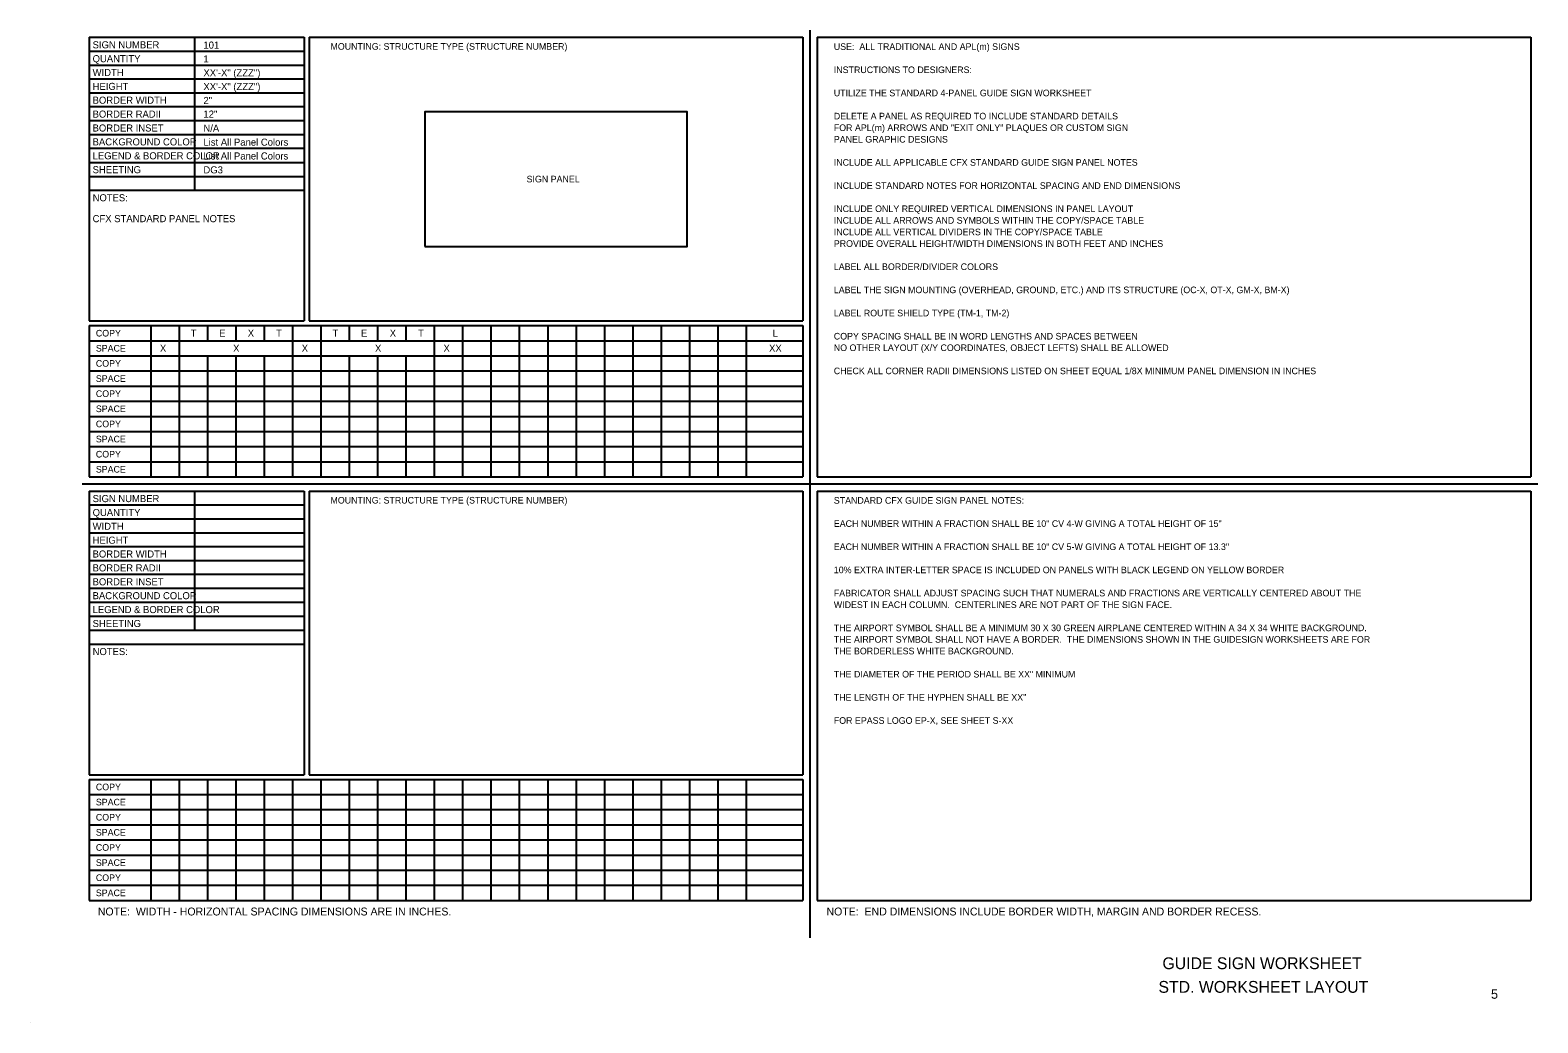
# Model space of a CAD drawing. Extents: x 10268312 to 10268472, y 2142583 to 2142688.
import ezdxf

# ---------------------------------------------------------------- set-up
doc = ezdxf.new("R2010")
doc.units = 0
for name, color, linetype in [('AdhocPoint_dp', 7, 'Continuous'), ('GSDims', 7, 'Continuous'), ('SheetBorder_dp', 7, 'Continuous'), ('SumBoxLines_dp', 7, 'Continuous'), ('SumBoxLinesMin_dp', 7, 'Continuous'), ('TextMisc', 7, 'Continuous'), ('TextNotes', 7, 'Continuous'), ('TextShtNo', 7, 'Continuous')]:
    doc.layers.add(name, color=color, linetype=linetype)

msp = doc.modelspace()

# ---------------------------------------------------------------- linework, layer by layer
at = {"layer": 'AdhocPoint_dp'}
msp.add_line((10268312.23, 2142583.28), (10268312.23, 2142583.28), dxfattribs=at)
at = {"layer": 'SheetBorder_dp'}
for p, q in [((10268394.73, 2142688.28), (10268394.73, 2142592.28)), ((10268317.73, 2142640.28), (10268471.73, 2142640.28))]:
    msp.add_line(p, q, dxfattribs=at)
at = {"layer": 'SumBoxLines_dp'}
for p, q in [((10268318.48, 2142687.53), (10268318.48, 2142657.53)), ((10268318.48, 2142687.53), (10268341.23, 2142687.53)), ((10268329.6, 2142687.53), (10268329.6, 2142671.34)), ((10268341.23, 2142687.53), (10268341.23, 2142657.53)), ((10268341.73, 2142687.53), (10268341.73, 2142657.53)), ((10268341.73, 2142687.53), (10268393.98, 2142687.53)), ((10268393.98, 2142687.53), (10268393.98, 2142657.53)), ((10268395.48, 2142687.53), (10268470.98, 2142687.53)), ((10268395.48, 2142687.53), (10268395.48, 2142641.03)), ((10268470.98, 2142687.53), (10268470.98, 2142641.03)), ((10268318.48, 2142686.07), (10268341.23, 2142686.07)), ((10268318.48, 2142684.59), (10268341.23, 2142684.59)), ((10268318.48, 2142683.12), (10268341.23, 2142683.12)), ((10268318.48, 2142681.66), (10268341.23, 2142681.66)), ((10268318.48, 2142680.19), (10268341.23, 2142680.19)), ((10268318.48, 2142678.73), (10268341.23, 2142678.73)), ((10268318.48, 2142677.26), (10268341.23, 2142677.26)), ((10268318.48, 2142675.79), (10268341.23, 2142675.79)), ((10268318.48, 2142674.28), (10268341.23, 2142674.28)), ((10268318.48, 2142672.81), (10268341.23, 2142672.81)), ((10268318.48, 2142671.34), (10268341.23, 2142671.34)), ((10268318.48, 2142657.53), (10268341.23, 2142657.53)), ((10268341.73, 2142657.53), (10268393.98, 2142657.53)), ((10268318.48, 2142657.03), (10268393.98, 2142657.03)), ((10268318.48, 2142657.03), (10268318.48, 2142641.03)), ((10268324.98, 2142657.03), (10268324.98, 2142641.03)), ((10268327.98, 2142657.03), (10268327.98, 2142641.03)), ((10268330.98, 2142657.03), (10268330.98, 2142655.43)), ((10268333.98, 2142657.03), (10268333.98, 2142655.43)), ((10268336.98, 2142657.03), (10268336.98, 2142655.43)), ((10268339.98, 2142657.03), (10268339.98, 2142653.83)), ((10268342.98, 2142657.03), (10268342.98, 2142653.83)), ((10268345.98, 2142657.03), (10268345.98, 2142655.43)), ((10268348.98, 2142657.03), (10268348.98, 2142655.43)), ((10268351.98, 2142657.03), (10268351.98, 2142655.43)), ((10268354.98, 2142657.03), (10268354.98, 2142655.43)), ((10268357.98, 2142657.03), (10268357.98, 2142655.43)), ((10268360.98, 2142657.03), (10268360.98, 2142653.83)), ((10268363.98, 2142657.03), (10268363.98, 2142653.83)), ((10268366.98, 2142657.03), (10268366.98, 2142653.83)), ((10268369.98, 2142657.03), (10268369.98, 2142653.83)), ((10268372.98, 2142657.03), (10268372.98, 2142655.43)), ((10268375.98, 2142657.03), (10268375.98, 2142655.43)), ((10268378.98, 2142657.03), (10268378.98, 2142655.43)), ((10268381.98, 2142657.03), (10268381.98, 2142655.43)), ((10268384.98, 2142657.03), (10268384.98, 2142655.43)), ((10268387.98, 2142657.03), (10268387.98, 2142655.43)), ((10268393.98, 2142657.03), (10268393.98, 2142641.03)), ((10268354.98, 2142655.43), (10268354.98, 2142641.03)), ((10268357.98, 2142655.43), (10268357.98, 2142641.03)), ((10268372.98, 2142655.43), (10268372.98, 2142641.03)), ((10268375.98, 2142655.43), (10268375.98, 2142641.03)), ((10268378.98, 2142655.43), (10268378.98, 2142649.03)), ((10268381.98, 2142655.43), (10268381.98, 2142649.03)), ((10268384.98, 2142655.43), (10268384.98, 2142649.03)), ((10268387.98, 2142655.43), (10268387.98, 2142641.03)), ((10268318.48, 2142653.83), (10268393.98, 2142653.83)), ((10268330.98, 2142653.83), (10268330.98, 2142641.03)), ((10268333.98, 2142653.83), (10268333.98, 2142641.03)), ((10268336.98, 2142653.83), (10268336.98, 2142641.03)), ((10268339.98, 2142653.83), (10268339.98, 2142641.03)), ((10268342.98, 2142653.83), (10268342.98, 2142641.03)), ((10268345.98, 2142653.83), (10268345.98, 2142641.03)), ((10268348.98, 2142653.83), (10268348.98, 2142641.03)), ((10268351.98, 2142653.83), (10268351.98, 2142641.03)), ((10268360.98, 2142653.83), (10268360.98, 2142641.03)), ((10268363.98, 2142653.83), (10268363.98, 2142641.03)), ((10268366.98, 2142653.83), (10268366.98, 2142649.03)), ((10268369.98, 2142653.83), (10268369.98, 2142649.03)), ((10268318.48, 2142650.63), (10268393.98, 2142650.63)), ((10268366.98, 2142649.03), (10268366.98, 2142641.03)), ((10268369.98, 2142649.03), (10268369.98, 2142641.03)), ((10268378.98, 2142649.03), (10268378.98, 2142641.03)), ((10268381.98, 2142649.03), (10268381.98, 2142641.03)), ((10268384.98, 2142649.03), (10268384.98, 2142641.03)), ((10268318.48, 2142647.43), (10268393.98, 2142647.43)), ((10268318.48, 2142644.23), (10268393.98, 2142644.23)), ((10268318.48, 2142641.03), (10268393.98, 2142641.03)), ((10268395.48, 2142641.03), (10268470.98, 2142641.03)), ((10268318.48, 2142639.53), (10268318.48, 2142609.53)), ((10268318.48, 2142639.53), (10268341.23, 2142639.53)), ((10268318.48, 2142638.07), (10268341.23, 2142638.07)), ((10268329.6, 2142639.53), (10268329.6, 2142624.81)), ((10268341.23, 2142639.53), (10268341.23, 2142609.53)), ((10268341.73, 2142639.53), (10268341.73, 2142609.53)), ((10268341.73, 2142639.53), (10268393.98, 2142639.53)), ((10268393.98, 2142639.53), (10268393.98, 2142609.53)), ((10268395.48, 2142639.53), (10268395.48, 2142596.23)), ((10268395.48, 2142639.53), (10268470.98, 2142639.53)), ((10268470.98, 2142639.53), (10268470.98, 2142596.23)), ((10268318.48, 2142636.59), (10268341.23, 2142636.59)), ((10268318.48, 2142635.12), (10268341.23, 2142635.12)), ((10268318.48, 2142633.66), (10268341.23, 2142633.66)), ((10268318.48, 2142632.19), (10268341.23, 2142632.19)), ((10268318.48, 2142630.73), (10268341.23, 2142630.73)), ((10268318.48, 2142629.26), (10268341.23, 2142629.26)), ((10268318.48, 2142627.79), (10268341.23, 2142627.79)), ((10268318.48, 2142626.28), (10268341.23, 2142626.28)), ((10268318.48, 2142624.81), (10268341.23, 2142624.81)), ((10268318.48, 2142623.34), (10268341.23, 2142623.34)), ((10268318.48, 2142609.53), (10268341.23, 2142609.53)), ((10268341.73, 2142609.53), (10268393.98, 2142609.53)), ((10268318.48, 2142609.03), (10268393.98, 2142609.03)), ((10268318.48, 2142609.03), (10268318.48, 2142596.23)), ((10268324.98, 2142609.03), (10268324.98, 2142596.23)), ((10268327.98, 2142609.03), (10268327.98, 2142596.23)), ((10268330.98, 2142609.03), (10268330.98, 2142596.23)), ((10268333.98, 2142609.03), (10268333.98, 2142596.23)), ((10268336.98, 2142609.03), (10268336.98, 2142596.23)), ((10268339.98, 2142609.03), (10268339.98, 2142596.23)), ((10268342.98, 2142609.03), (10268342.98, 2142596.23)), ((10268345.98, 2142609.03), (10268345.98, 2142596.23)), ((10268348.98, 2142609.03), (10268348.98, 2142596.23)), ((10268351.98, 2142609.03), (10268351.98, 2142596.23)), ((10268354.98, 2142609.03), (10268354.98, 2142596.23)), ((10268357.98, 2142609.03), (10268357.98, 2142596.23)), ((10268360.98, 2142609.03), (10268360.98, 2142596.23)), ((10268363.98, 2142609.03), (10268363.98, 2142596.23)), ((10268366.98, 2142609.03), (10268366.98, 2142596.23)), ((10268369.98, 2142609.03), (10268369.98, 2142596.23)), ((10268372.98, 2142609.03), (10268372.98, 2142596.23)), ((10268375.98, 2142609.03), (10268375.98, 2142596.23)), ((10268378.98, 2142609.03), (10268378.98, 2142596.23)), ((10268381.98, 2142609.03), (10268381.98, 2142596.23)), ((10268384.98, 2142609.03), (10268384.98, 2142596.23)), ((10268387.98, 2142609.03), (10268387.98, 2142607.43)), ((10268393.98, 2142609.03), (10268393.98, 2142596.23)), ((10268387.98, 2142607.43), (10268387.98, 2142596.23)), ((10268318.48, 2142605.83), (10268393.98, 2142605.83)), ((10268318.48, 2142602.63), (10268393.98, 2142602.63)), ((10268318.48, 2142599.43), (10268393.98, 2142599.43)), ((10268318.48, 2142596.23), (10268393.98, 2142596.23)), ((10268395.48, 2142596.23), (10268470.98, 2142596.23))]:
    msp.add_line(p, q, dxfattribs=at)
at = {"layer": 'SumBoxLinesMin_dp'}
for p, q in [((10268318.48, 2142655.43), (10268393.98, 2142655.43)), ((10268318.48, 2142652.23), (10268393.98, 2142652.23)), ((10268318.48, 2142649.03), (10268393.98, 2142649.03)), ((10268318.48, 2142645.83), (10268393.98, 2142645.83)), ((10268318.48, 2142642.63), (10268393.98, 2142642.63)), ((10268318.48, 2142607.43), (10268393.98, 2142607.43)), ((10268318.48, 2142604.23), (10268393.98, 2142604.23)), ((10268318.48, 2142601.03), (10268393.98, 2142601.03)), ((10268318.48, 2142597.83), (10268393.98, 2142597.83))]:
    msp.add_line(p, q, dxfattribs=at)
at = {"layer": 'TextMisc'}
msp.add_lwpolyline([(10268353.98, 2142665.41), (10268381.73, 2142665.41), (10268381.73, 2142679.66), (10268353.98, 2142679.66)], close=True, dxfattribs=at)

# ---------------------------------------------------------------- texts
at = {"layer": 'GSDims'}
for s, height, p in [('MOUNTING: STRUCTURE TYPE (STRUCTURE NUMBER)', 0.7, (10268344, 2142686.21)), ('SIGN PANEL', 0.7, (10268364.75, 2142672.18)), ('T', 0.75, (10268329.21, 2142655.86)), ('E', 0.75, (10268332.22, 2142655.86)), ('X', 0.75, (10268335.25, 2142655.86)), ('T', 0.75, (10268338.25, 2142655.86)), ('T', 0.75, (10268344.22, 2142655.86)), ('E', 0.75, (10268347.23, 2142655.86)), ('X', 0.75, (10268350.27, 2142655.86)), ('T', 0.75, (10268353.27, 2142655.86)), ('L', 0.75, (10268390.77, 2142655.86)), ('X', 0.75, (10268325.96, 2142654.26)), ('X', 0.75, (10268333.7, 2142654.26)), ('X', 0.75, (10268340.96, 2142654.26)), ('X', 0.75, (10268348.71, 2142654.26)), ('X', 0.75, (10268355.96, 2142654.26)), ('XX', 0.75, (10268390.4, 2142654.26)), ('MOUNTING: STRUCTURE TYPE (STRUCTURE NUMBER)', 0.7, (10268344, 2142638.21))]:
    msp.add_text(s, height=height, dxfattribs=at).set_placement(p)
at = {"layer": 'TextMisc'}
for s, height, p in [('SIGN NUMBER', 0.7476, (10268318.84, 2142686.36)), ('101', 0.75, (10268330.56, 2142686.33)), ('USE:  ALL TRADITIONAL AND APL(m) SIGNS', 0.7, (10268397.25, 2142686.19)), ('QUANTITY', 0.748, (10268318.84, 2142684.89)), ('1', 0.75, (10268330.56, 2142684.87)), ('INSTRUCTIONS TO DESIGNERS:', 0.7, (10268397.25, 2142683.74)), ('WIDTH', 0.748, (10268318.84, 2142683.43)), ('HEIGHT', 0.748, (10268318.84, 2142681.96)), ('XX\'-X" (ZZZ")', 0.75, (10268330.56, 2142683.4)), ('XX\'-X" (ZZZ")', 0.75, (10268330.56, 2142681.94)), ('BORDER WIDTH', 0.7476, (10268318.84, 2142680.5)), ('2"', 0.75, (10268330.56, 2142680.47)), ('UTILIZE THE STANDARD 4-PANEL GUIDE SIGN WORKSHEET', 0.7, (10268397.25, 2142681.29)), ('BORDER RADII', 0.7476, (10268318.84, 2142679.03)), ('12"', 0.75, (10268330.56, 2142679.03)), ('DELETE A PANEL AS REQUIRED TO INCLUDE STANDARD DETAILS', 0.7, (10268397.25, 2142678.84)), ('BORDER INSET', 0.7476, (10268318.84, 2142677.56)), ('N/A', 0.75, (10268330.56, 2142677.53)), ('FOR APL(m) ARROWS AND "EXIT ONLY" PLAQUES OR CUSTOM SIGN', 0.7, (10268397.25, 2142677.61)), ('BACKGROUND COLOR', 0.7476, (10268318.84, 2142676.09)), ('List All Panel Colors', 0.75, (10268330.56, 2142676.06)), ('PANEL GRAPHIC DESIGNS', 0.7, (10268397.25, 2142676.39)), ('LEGEND & BORDER COLOR', 0.7476, (10268318.84, 2142674.62)), ('List All Panel Colors', 0.75, (10268330.56, 2142674.6)), ('INCLUDE ALL APPLICABLE CFX STANDARD GUIDE SIGN PANEL NOTES', 0.7, (10268397.25, 2142673.94)), ('SHEETING', 0.748, (10268318.84, 2142673.15)), ('DG3', 0.75, (10268330.56, 2142673.13)), ('INCLUDE STANDARD NOTES FOR HORIZONTAL SPACING AND END DIMENSIONS', 0.7, (10268397.25, 2142671.49)), ('NOTES:', 0.748, (10268318.84, 2142670.18)), ('CFX STANDARD PANEL NOTES', 0.75, (10268318.84, 2142667.97)), ('INCLUDE ONLY REQUIRED VERTICAL DIMENSIONS IN PANEL LAYOUT', 0.7, (10268397.25, 2142669.04)), ('INCLUDE ALL ARROWS AND SYMBOLS WITHIN THE COPY/SPACE TABLE', 0.7, (10268397.25, 2142667.81)), ('INCLUDE ALL VERTICAL DIVIDERS IN THE COPY/SPACE TABLE', 0.7, (10268397.25, 2142666.59)), ('PROVIDE OVERALL HEIGHT/WIDTH DIMENSIONS IN BOTH FEET AND INCHES', 0.7, (10268397.25, 2142665.36)), ('LABEL ALL BORDER/DIVIDER COLORS', 0.7, (10268397.25, 2142662.91)), ('LABEL THE SIGN MOUNTING (OVERHEAD, GROUND, ETC.) AND ITS STRUCTURE (OC-X, OT-X, GM-X, BM-X)', 0.7, (10268397.25, 2142660.46)), ('LABEL ROUTE SHIELD TYPE (TM-1, TM-2)', 0.7, (10268397.25, 2142658.01)), ('COPY', 0.7, (10268319.18, 2142655.88)), ('COPY SPACING SHALL BE IN WORD LENGTHS AND SPACES BETWEEN', 0.7, (10268397.25, 2142655.56)), ('SPACE', 0.7, (10268319.18, 2142654.28)), ('NO OTHER LAYOUT (X/Y COORDINATES, OBJECT LEFTS) SHALL BE ALLOWED', 0.7, (10268397.25, 2142654.34)), ('COPY', 0.7, (10268319.18, 2142652.68)), ('CHECK ALL CORNER RADII DIMENSIONS LISTED ON SHEET EQUAL 1/8X MINIMUM PANEL DIMENSION IN INCHES', 0.7, (10268397.25, 2142651.89)), ('SPACE', 0.7, (10268319.18, 2142651.08)), ('COPY', 0.7, (10268319.18, 2142649.48)), ('SPACE', 0.7, (10268319.18, 2142647.88)), ('COPY', 0.7, (10268319.18, 2142646.28)), ('SPACE', 0.7, (10268319.18, 2142644.68)), ('COPY', 0.7, (10268319.18, 2142643.08)), ('SPACE', 0.7, (10268319.18, 2142641.48)), ('SIGN NUMBER', 0.7476, (10268318.84, 2142638.36)), ('STANDARD CFX GUIDE SIGN PANEL NOTES:', 0.7, (10268397.25, 2142638.19)), ('QUANTITY', 0.748, (10268318.84, 2142636.89)), ('EACH NUMBER WITHIN A FRACTION SHALL BE 10" CV 4-W GIVING A TOTAL HEIGHT OF 15"', 0.7, (10268397.25, 2142635.74)), ('WIDTH', 0.748, (10268318.84, 2142635.43)), ('HEIGHT', 0.748, (10268318.84, 2142633.96)), ('BORDER WIDTH', 0.7476, (10268318.84, 2142632.5)), ('EACH NUMBER WITHIN A FRACTION SHALL BE 10" CV 5-W GIVING A TOTAL HEIGHT OF 13.3"', 0.7, (10268397.25, 2142633.29)), ('BORDER RADII', 0.7476, (10268318.84, 2142631.03)), ('BORDER INSET', 0.7476, (10268318.84, 2142629.56)), ('10% EXTRA INTER-LETTER SPACE IS INCLUDED ON PANELS WITH BLACK LEGEND ON YELLOW BORDER', 0.7, (10268397.25, 2142630.84)), ('BACKGROUND COLOR', 0.7476, (10268318.84, 2142628.09)), ('FABRICATOR SHALL ADJUST SPACING SUCH THAT NUMERALS AND FRACTIONS ARE VERTICALLY CENTERED ABOUT THE', 0.7, (10268397.25, 2142628.39)), ('LEGEND & BORDER COLOR', 0.7476, (10268318.84, 2142626.62)), ('WIDEST IN EACH COLUMN.  CENTERLINES ARE NOT PART OF THE SIGN FACE.', 0.7, (10268397.25, 2142627.16)), ('SHEETING', 0.748, (10268318.84, 2142625.15)), ('THE AIRPORT SYMBOL SHALL BE A MINIMUM 30 X 30 GREEN AIRPLANE CENTERED WITHIN A 34 X 34 WHITE BACKGROUND.', 0.7, (10268397.25, 2142624.71)), ('THE AIRPORT SYMBOL SHALL NOT HAVE A BORDER.  THE DIMENSIONS SHOWN IN THE GUIDESIGN WORKSHEETS ARE FOR', 0.7, (10268397.25, 2142623.49)), ('NOTES:', 0.748, (10268318.84, 2142622.18)), ('THE BORDERLESS WHITE BACKGROUND.', 0.7, (10268397.25, 2142622.26)), ('THE DIAMETER OF THE PERIOD SHALL BE XX" MINIMUM', 0.7, (10268397.25, 2142619.81)), ('THE LENGTH OF THE HYPHEN SHALL BE XX"', 0.7, (10268397.25, 2142617.36)), ('FOR EPASS LOGO EP-X, SEE SHEET S-XX', 0.7, (10268397.25, 2142614.91)), ('COPY', 0.7, (10268319.18, 2142607.88)), ('SPACE', 0.7, (10268319.18, 2142606.28)), ('COPY', 0.7, (10268319.18, 2142604.68)), ('SPACE', 0.7, (10268319.18, 2142603.08)), ('COPY', 0.7, (10268319.18, 2142601.48)), ('SPACE', 0.7, (10268319.18, 2142599.88)), ('COPY', 0.7, (10268319.18, 2142598.28)), ('SPACE', 0.7, (10268319.18, 2142596.68))]:
    msp.add_text(s, height=height, dxfattribs=at).set_placement(p)
for s, p in [('  GUIDE SIGN WORKSHEET  ', (10268431.09, 2142588.96)), (' STD. WORKSHEET LAYOUT  ', (10268431.13, 2142586.46))]:
    msp.add_text(s, height=1.25, rotation=360, dxfattribs=at).set_placement(p)
at = {"layer": 'TextNotes'}
for s, p in [('NOTE:  WIDTH - HORIZONTAL SPACING DIMENSIONS ARE IN INCHES.', (10268319.39, 2142594.64)), ('NOTE:  END DIMENSIONS INCLUDE BORDER WIDTH, MARGIN AND BORDER RECESS.  ', (10268396.48, 2142594.64))]:
    msp.add_text(s, height=0.8333, dxfattribs=at).set_placement(p)
at = {"layer": 'TextShtNo'}
msp.add_text('  5   ', height=1, rotation=360, dxfattribs=at).set_placement((10268466.03, 2142585.83))

doc.saveas('drawing.dxf')
